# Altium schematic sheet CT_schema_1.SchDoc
size 307 x 449 mm
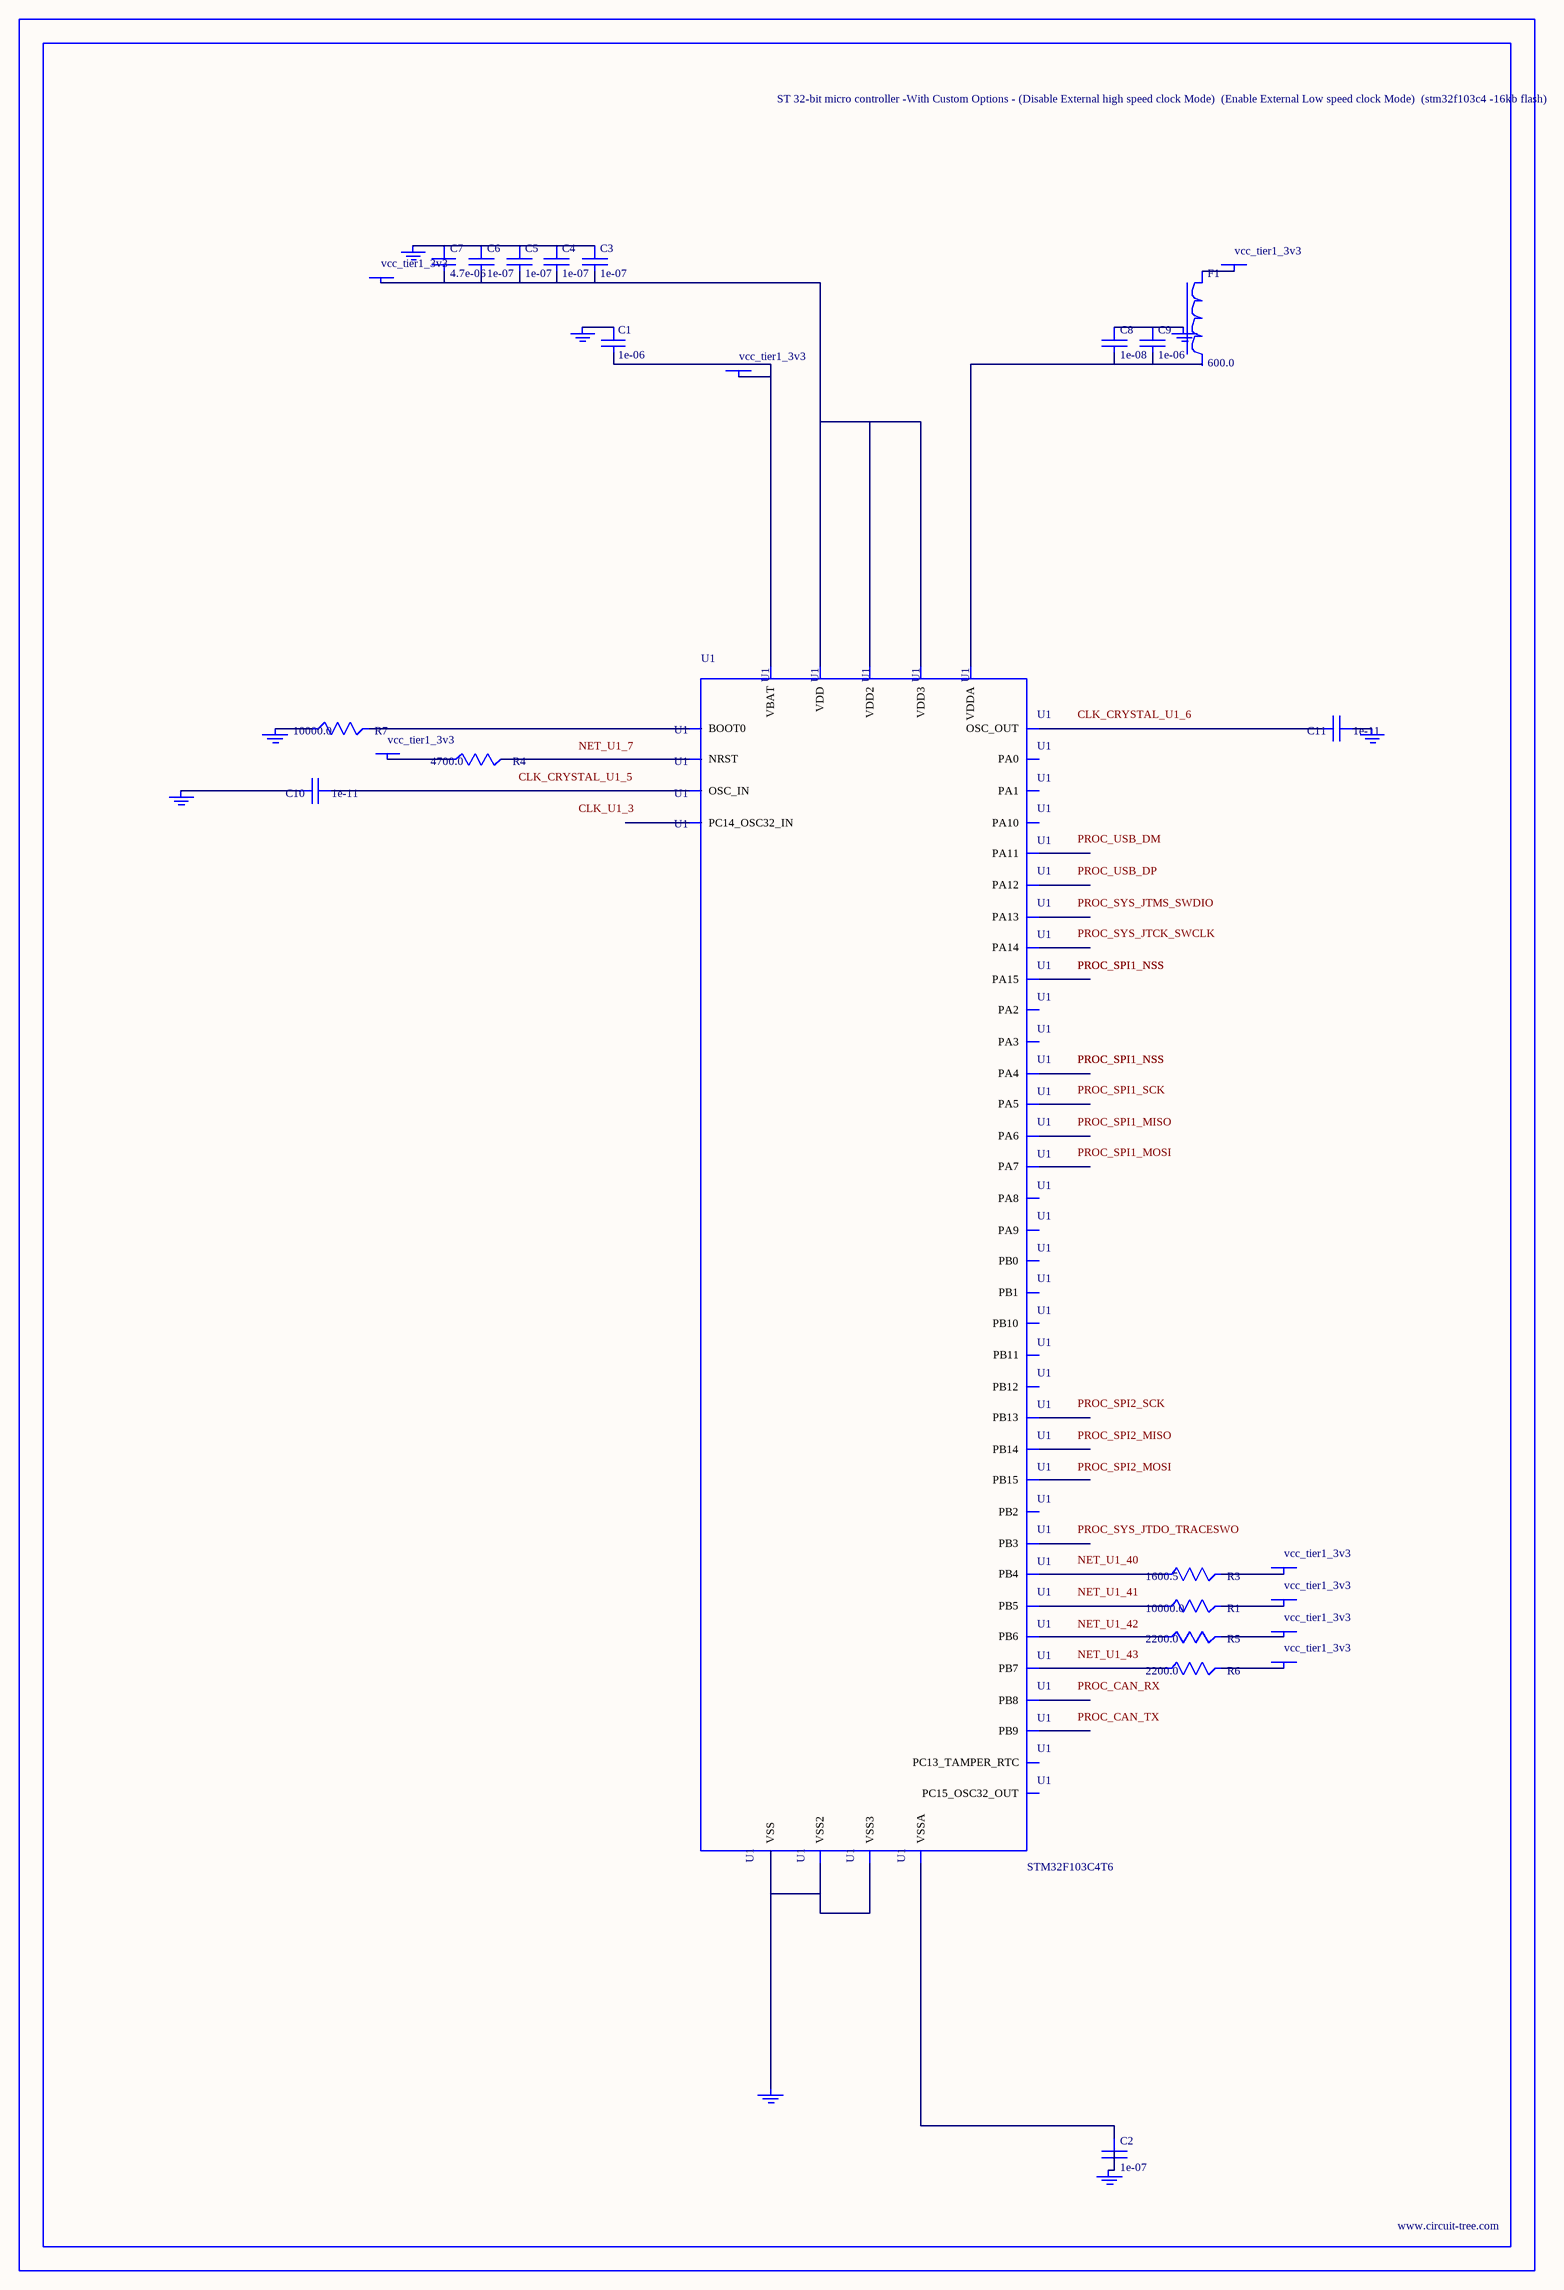
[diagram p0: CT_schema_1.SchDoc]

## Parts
BORDER0  (no value)
C1  1e-06  [C0603]
C2  1e-07  [C0402]
C3  1e-07  [C0402]
C4  1e-07  [C0402]
C5  1e-07  [C0402]
C6  1e-07  [C0402]
C7  4.7e-06  [C0603]
C8  1e-08  [C0603]
C9  1e-06  [C0603]
C10  1e-11  [C0402]
C11  1e-11  [C0402]
F1  600.0  [L0603]
GND_INSTANCE_0_0  (no value)
GND_INSTANCE_0_1  (no value)
GND_INSTANCE_0_2  (no value)
GND_INSTANCE_0_3  (no value)
GND_INSTANCE_0_4  (no value)
GND_INSTANCE_0_5  (no value)
GND_INSTANCE_0_6  (no value)
GND_INSTANCE_0_7  (no value)
POWER_INSTANCE_0_0  vcc_tier1_3v3
POWER_INSTANCE_0_1  vcc_tier1_3v3
POWER_INSTANCE_0_2  vcc_tier1_3v3
POWER_INSTANCE_0_3  vcc_tier1_3v3
POWER_INSTANCE_0_4  vcc_tier1_3v3
POWER_INSTANCE_0_5  vcc_tier1_3v3
POWER_INSTANCE_0_6  vcc_tier1_3v3
POWER_INSTANCE_0_7  vcc_tier1_3v3
R1  10000.0  [R0603]
R3  1600.5  [R0603]
R4  4700.0  [R0603]
R5  2200.0  [R0603]
R6  2200.0  [R0603]
R7  10000.0  [R0603]
U1  STM32F103C4T6  [LQFP48]

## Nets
NetC1_1: C1.1 GND_INSTANCE_0_0.0(GND)
NetC1_2: C1.2 POWER_INSTANCE_0_0.0(PWR) U1.1(VBAT)
NetC2_1: C2.1 U1.8(VSSA)
NetC2_2: C2.2 GND_INSTANCE_0_3.0(GND)
NetC3_1: C3.1 C4.1 C5.1 C6.1 C7.1 GND_INSTANCE_0_5.0(GND)
NetC3_2: C3.2 C4.2 C5.2 C6.2 C7.2 POWER_INSTANCE_0_2.0(PWR) U1.24(VDD) U1.36(VDD2) U1.48(VDD3)
NetC8_1: C8.1 C9.1 GND_INSTANCE_0_4.0(GND)
NetC8_2: C8.2 C9.2 U1.9(VDDA)
NetC10_1: C10.1 U1.5(OSC_IN)
NetC10_2: C10.2 GND_INSTANCE_0_1.0(GND)
NetC11_1: C11.1 GND_INSTANCE_0_2.0(GND)
NetC11_2: C11.2 U1.6(OSC_OUT)
NetF1_1: F1.1 POWER_INSTANCE_0_1.0(PWR)
NetGND_INSTANCE_0_6_0: GND_INSTANCE_0_6.0(GND) R7.1
NetGND_INSTANCE_0_7_0: GND_INSTANCE_0_7.0(GND) U1.23(VSS) U1.35(VSS2) U1.47(VSS3)
NetPOWER_INSTANCE_0_3_0: POWER_INSTANCE_0_3.0(PWR) R4.1
NetPOWER_INSTANCE_0_4_0: POWER_INSTANCE_0_4.0(PWR) R3.2
NetPOWER_INSTANCE_0_5_0: POWER_INSTANCE_0_5.0(PWR) R1.2
NetPOWER_INSTANCE_0_6_0: POWER_INSTANCE_0_6.0(PWR) R5.2
NetPOWER_INSTANCE_0_7_0: POWER_INSTANCE_0_7.0(PWR) R6.2
NetR1_1: R1.1 U1.41(PB5)
NetR3_1: R3.1 U1.40(PB4)
NetR4_2: R4.2 U1.7(NRST)
NetR5_1: R5.1 U1.42(PB6)
NetR6_1: R6.1 U1.43(PB7)
NetR7_2: R7.2 U1.44(BOOT0)

Not connected (* = marked no-connect by the designer): F1 2; U1 2(PC13_TAMPER_RTC) 3(PC14_OSC32_IN) 4(PC15_OSC32_OUT) 10(PA0) 11(PA1) 12(PA2) 13(PA3) 14(PA4) 15(PA5) 16(PA6) 17(PA7) 18(PB0) 19(PB1) 20(PB2) 21(PB10) 22(PB11) 25(PB12) 26(PB13) 27(PB14) 28(PB15) 29(PA8) 30(PA9) 31(PA10) 32(PA11) 33(PA12) 34(PA13) 37(PA14) 38(PA15) 39(PB3) 45(PB8) 46(PB9)

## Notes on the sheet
- Labels drawn without touching a wire or pin: CLK_CRYSTAL_U1_5, CLK_CRYSTAL_U1_6, CLK_U1_3, NET_U1_7, NET_U1_40, NET_U1_41, NET_U1_42, NET_U1_43, PROC_CAN_RX, PROC_CAN_TX, PROC_SPI1_MISO, PROC_SPI1_MOSI, PROC_SPI1_SCK, PROC_SPI2_MISO, PROC_SPI2_MOSI, PROC_SPI2_SCK, PROC_SYS_JTCK_SWCLK, PROC_SYS_JTDO_TRACESWO, PROC_SYS_JTMS_SWDIO, PROC_USB_DM, PROC_USB_DP

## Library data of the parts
BORDER0 = BORDER_PAGE0
C1 C9 = C0603C105K3RACTU
C2-C6 = C0402C104K3RACTU
C7 = GRM188R6YA475KE15D
C8 = 06035C103K4Z2A
C10 C11 = C0402C100K3GACTU
F1 = Z0603C601ASMST
GND_INSTANCE_0_0-GND_INSTANCE_0_7 = GND
POWER_INSTANCE_0_0-POWER_INSTANCE_0_7 = PWR
R1 R7 = RC0603JR-0710KL
R3 = R3
R4 = RC0603JR-074K7L
R5 R6 = RC0603JR-072K2L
